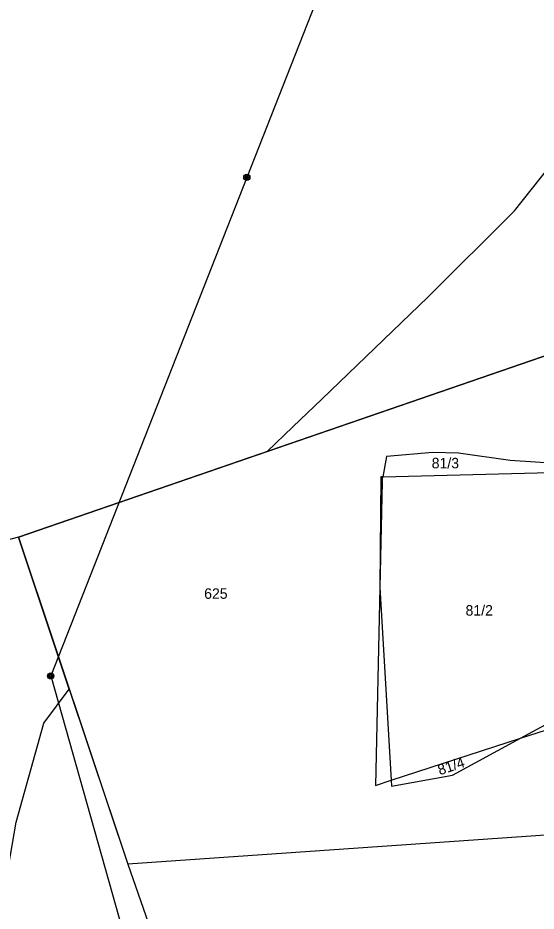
# Model space of a CAD drawing. Extents: x -725765 to -723182, y -1052705 to -1049154.
# Drawn here: x -725049.2 to -724965.3, y -1050916.4 to -1050771.8 of the extents above; entities that cross this region are included whole.
import ezdxf

# ---------------------------------------------------------------- set-up
doc = ezdxf.new("R2010")
doc.units = 0
for name, color, linetype in [('Vrstva 1', 7, 'Continuous'), ('Vrstva 12', 7, 'Continuous'), ('Vrstva 18', 7, 'Continuous'), ('Vrstva 25', 7, 'Continuous'), ('Vrstva 4', 7, 'Continuous'), ('Vrstva 52', 7, 'Continuous')]:
    doc.layers.add(name, color=color, linetype=linetype)

msp = doc.modelspace()

# ---------------------------------------------------------------- linework, layer by layer
at = {"layer": 'Vrstva 1'}
for points in [[(-724957.9, -1050824.41), (-725049.13, -1050855.87)], [(-724982.07, -1050842.13), (-724989.53, -1050842.79)], [(-724977.9, -1050842.27), (-724982.07, -1050842.13)], [(-724969.55, -1050843.44), (-724977.9, -1050842.27)], [(-724989.53, -1050842.79), (-724990.13, -1050846.08)], [(-724958.82, -1050844.16), (-724969.55, -1050843.44)], [(-724990.13, -1050846.08), (-724958.87, -1050845.29)], [(-724990.44, -1050846.09), (-724990.64, -1050864.03)], [(-724990.13, -1050846.08), (-724990.44, -1050846.09)], [(-725049.13, -1050855.87), (-725230.63, -1050903.55)], [(-725049.13, -1050855.87), (-725031.43, -1050908.84)], [(-724990.64, -1050864.03), (-724991.35, -1050896.06)], [(-724967.87, -1050888.42), (-724959.62, -1050885.74)], [(-724988.78, -1050895.22), (-724967.87, -1050888.42)], [(-724978.89, -1050894.4), (-724967.87, -1050888.42)], [(-724988.72, -1050896.19), (-724978.89, -1050894.4)], [(-724991.35, -1050896.06), (-724988.78, -1050895.22)], [(-724988.78, -1050895.22), (-724988.72, -1050896.19)], [(-724961.46, -1050903.95), (-725031.43, -1050908.84)], [(-725031.43, -1050908.84), (-724999.85, -1050999.45)]]:
    msp.add_lwpolyline(points, dxfattribs=at)
at = {"layer": 'Vrstva 12'}
for points in [[(-724980.97, -1050718.23), (-725012.16, -1050797.58)], [(-725012.16, -1050797.58), (-725043.92, -1050878.32)], [(-725043.92, -1050878.32), (-725024.03, -1050948.77)]]:
    msp.add_lwpolyline(points, dxfattribs=at)
at = {"layer": 'Vrstva 25'}
for centre, radius in [((-725012.16, -1050797.58), 0.5), ((-725012.16, -1050797.58), 0.3), ((-725012.16, -1050797.58), 0.15), ((-725043.92, -1050878.32), 0.5), ((-725043.92, -1050878.32), 0.3), ((-725043.92, -1050878.32), 0.15)]:
    msp.add_circle(centre, radius, dxfattribs=at)
at = {"layer": 'Vrstva 4'}
for points in [[(-724990.27, -1050846.87), (-724990.64, -1050864.03)], [(-724990.44, -1050846.09), (-724990.27, -1050846.87)], [(-724990.27, -1050846.87), (-724990.13, -1050846.08)], [(-724990.64, -1050864.03), (-724988.78, -1050895.22)], [(-724967.87, -1050888.42), (-724959.77, -1050884.03)]]:
    msp.add_lwpolyline(points, dxfattribs=at)
at = {"layer": 'Vrstva 52'}
for points in [[(-725008.87, -1050841.99), (-725004.69, -1050838), (-725000, -1050833.49), (-724982.88, -1050817), (-724968.81, -1050803), (-724956.13, -1050787), (-724949, -1050774), (-724939.38, -1050753), (-724937.5, -1050742), (-724937.5, -1050735), (-724940.13, -1050730), (-724944.5, -1050729), (-724951.63, -1050730), (-724977.19, -1050734), (-724995.13, -1050740), (-725000, -1050742.11), (-725022.88, -1050752), (-725054.63, -1050765)], [(-725008.87, -1050841.99), (-724957.9, -1050824.41), (-724958.13, -1050829.41), (-724958.82, -1050844.16), (-724969.55, -1050843.44), (-724977.9, -1050842.27), (-724982.07, -1050842.13), (-724989.53, -1050842.79), (-724990.13, -1050846.08), (-724990.44, -1050846.09), (-724990.64, -1050864.03), (-724991.35, -1050896.06), (-724988.78, -1050895.22), (-724988.72, -1050896.19), (-724978.89, -1050894.4), (-724967.87, -1050888.42), (-724959.62, -1050885.74), (-724959.03, -1050885.42), (-724956.19, -1050890.69), (-724954.81, -1050893.27)], [(-725040.9, -1050880.49), (-725049.13, -1050855.87), (-725008.87, -1050841.99)], [(-725222.31, -1051084), (-725204.74, -1051077.08), (-725195.29, -1051073.36), (-725189.31, -1051071), (-725147.13, -1051053), (-725104.19, -1051030), (-725082.38, -1051016), (-725065.81, -1050999), (-725051.38, -1050977), (-725045.63, -1050964), (-725045, -1050955), (-725045, -1050943), (-725049.5, -1050927), (-725051.38, -1050913), (-725049.5, -1050902), (-725045, -1050886), (-725040.9, -1050880.49)], [(-725040.9, -1050880.49), (-725031.43, -1050908.84), (-724999.85, -1050999.45), (-724994.58, -1050998.09), (-724994.29, -1050994.27), (-724993.62, -1050987.89), (-724992.12, -1050978.69), (-724959.02, -1050935.48), (-724959.3, -1050931.91), (-724960.13, -1050921.08), (-724961.29, -1050906.08), (-724961.46, -1050903.95), (-724954.82, -1050902.24)]]:
    msp.add_lwpolyline(points, dxfattribs=at)

# ---------------------------------------------------------------- texts
at = {"layer": 'Vrstva 18'}
for s, p in [('81/3', (-724982.23, -1050844.71)), ('625', (-725019.07, -1050865.84)), ('81/2', (-724976.75, -1050868.56))]:
    msp.add_text(s, height=1.7, dxfattribs=at).set_placement(p)
msp.add_text('81/4', height=1.7, rotation=18.5001, dxfattribs=at).set_placement((-724980.92, -1050894.43))

doc.saveas('drawing.dxf')
